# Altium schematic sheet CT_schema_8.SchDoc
size 370 x 245 mm
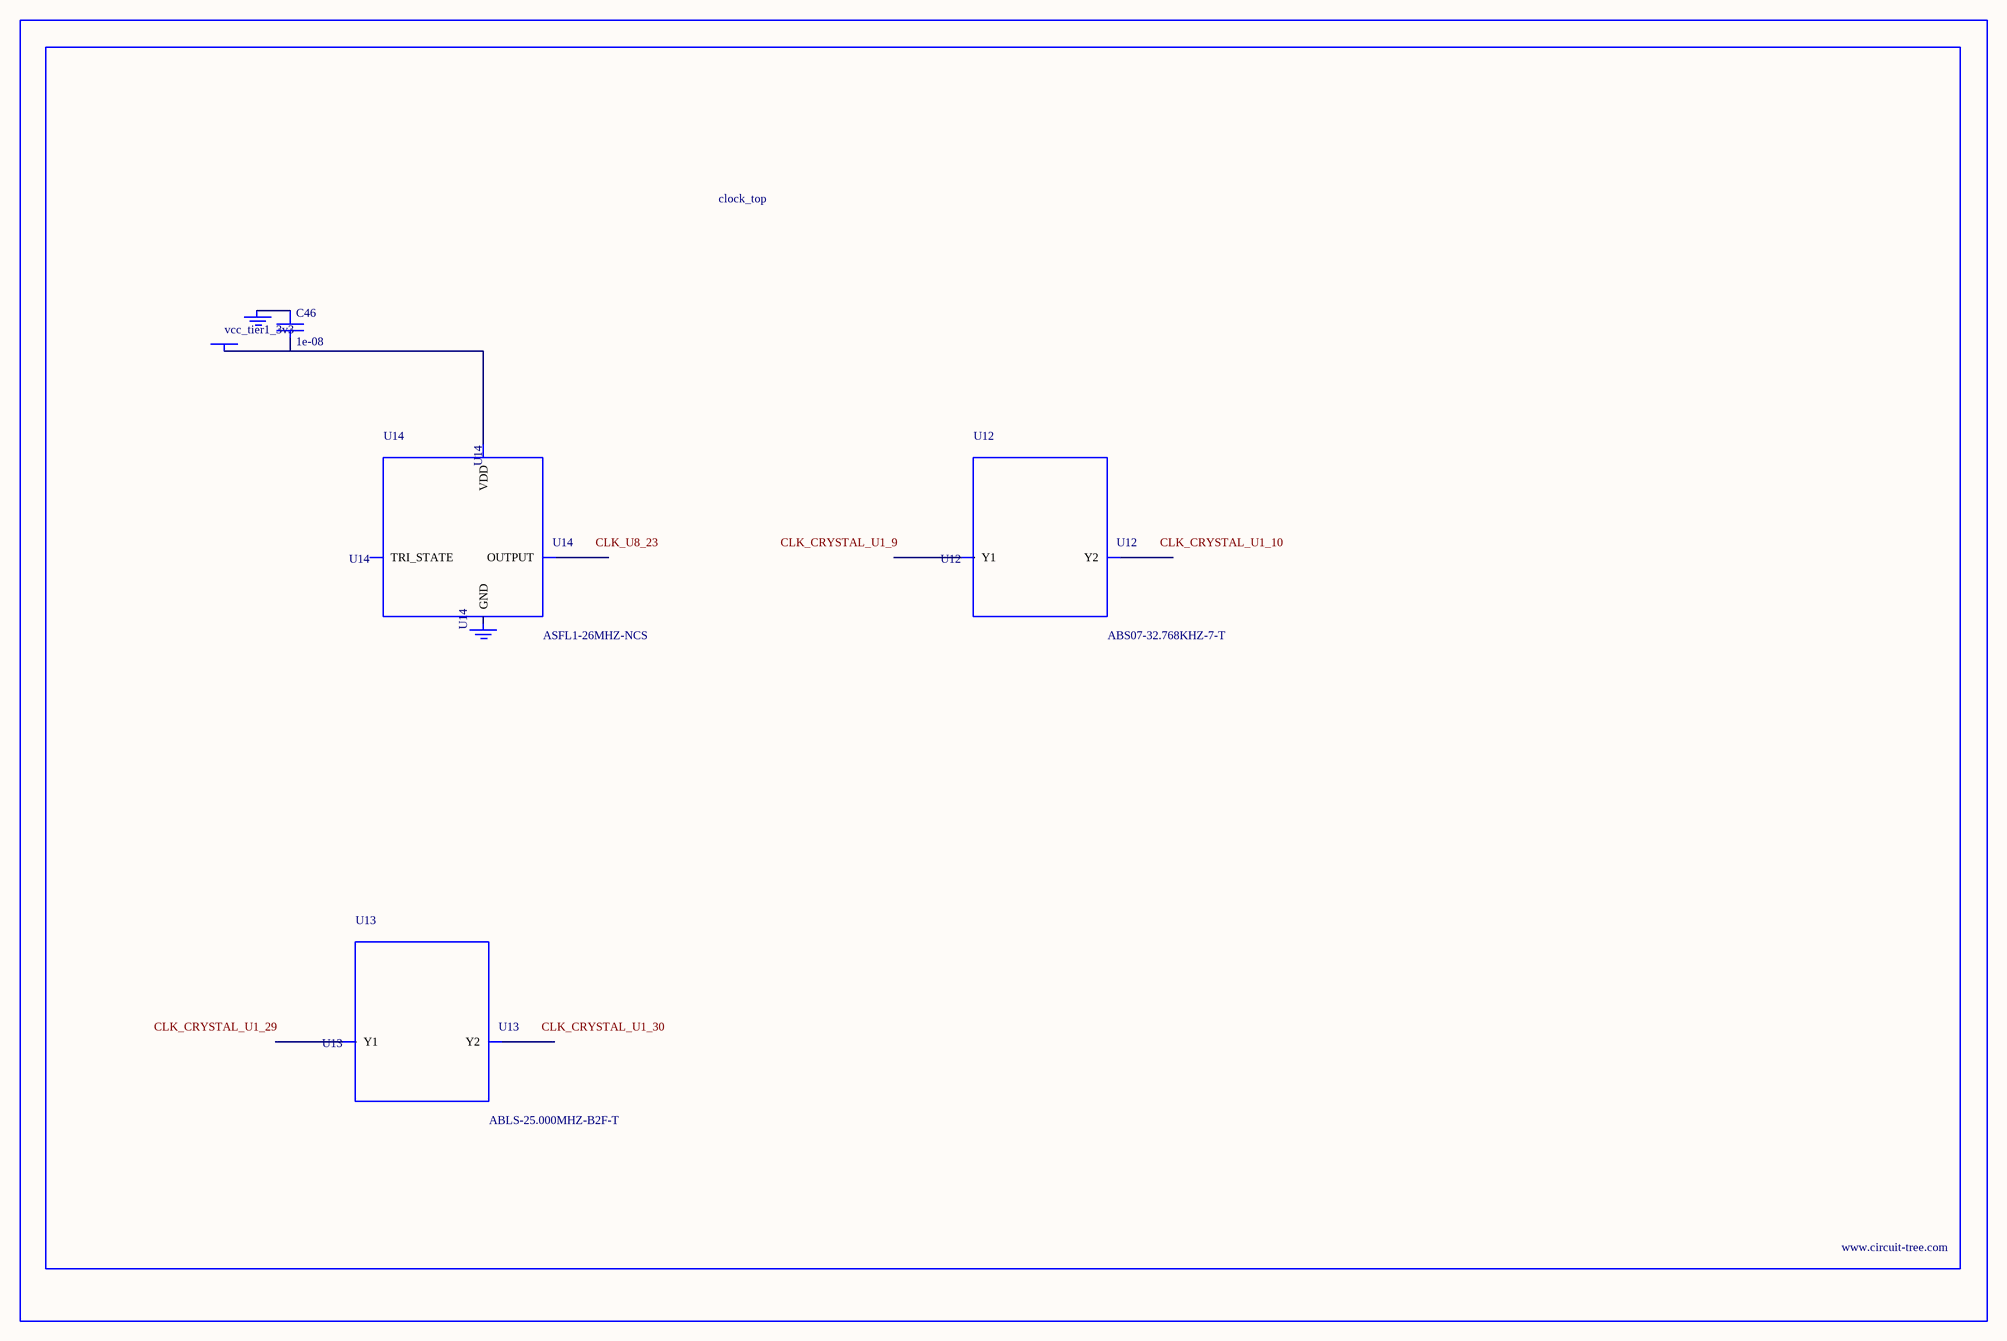
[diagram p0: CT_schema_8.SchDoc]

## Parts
BORDER7  (no value)
C46  1e-08  [C0402]
GND_INSTANCE_7_0  (no value)
GND_INSTANCE_7_1  (no value)
POWER_INSTANCE_7_0  vcc_tier1_3v3
U12  ABS07-32.768KHZ-7-T  [ABS07-32.768KHZ-7-T]
U13  ABLS-25.000MHZ-B2F-T  [ABLS-25.000MHZ-B2F-T]
U14  ASFL1-26MHZ-NCS  [ASFL1]

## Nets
NetC46_1: C46.1 GND_INSTANCE_7_0.0(GND)
NetC46_2: C46.2 POWER_INSTANCE_7_0.0(PWR) U14.4(VDD)

Not connected (* = marked no-connect by the designer): GND_INSTANCE_7_1 0(GND); U12 1(Y1) 2(Y2); U13 1(Y1) 2(Y2); U14 1(TRI_STATE) 2(GND) 3(OUTPUT)

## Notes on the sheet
- Labels drawn without touching a wire or pin: CLK_CRYSTAL_U1_9, CLK_CRYSTAL_U1_10, CLK_CRYSTAL_U1_29, CLK_CRYSTAL_U1_30, CLK_U8_23

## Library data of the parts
BORDER7 = BORDER_PAGE7
C46 = C0402C103K3RAC
GND_INSTANCE_7_0 GND_INSTANCE_7_1 = GND
POWER_INSTANCE_7_0 = PWR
